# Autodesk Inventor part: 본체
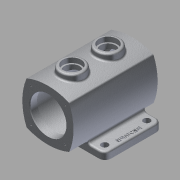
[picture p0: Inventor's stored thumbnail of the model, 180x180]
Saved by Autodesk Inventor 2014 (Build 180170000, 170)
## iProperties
Created: 2013-02
Part Number: 본체
Document SubType Name: Modeling
Designer: 한국산업디자인학원[gmhk.co.kr]
Density: 2.71 g/cm^3
Material: 알루미늄 6061
Mass: 1212.59 g
Surface Area: 1019.32 cm^2
Volume: 447.452 cm^3
Appearance: _시험_알루미늄 표면거칠기
Author: 한국산업디자인학원[gmhk.co.kr]
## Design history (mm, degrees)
sketch "스케치1"
  geometry: L1 (-65, 55)-(65, 55); L2 (65, 55)-(65, -40); L3 (65, -40)-(-65, -40); L4 (-65, -40)-(-65, 55); 2 further points
  constraints: 8 end point, 2 parallel, 1 horizontal, 1 midpoint, 1 perpendicular, 1 vertical alignment
  dimensions: "d0" = 130 distance of L2.end L3.end; "d1" = 95 distance of L1.end L2.end; "d47" = 40 distance from line of L3 point (0, 0)
extrude "돌출1" new body sketch "스케치1" distance "d2" = 12; taper "d3" = 0 deg
sketch "스케치2"
  geometry: L1 (-35.355, 85.355)-(35.355, 85.355); L2 (35.355, 85.355)-(35.355, 14.645); L3 (35.355, 14.645)-(-35.355, 14.645); L4 (-35.355, 14.645)-(-35.355, 85.355); L5 (35.355, 85.355)-(-35.355, 14.645); L6 (65, 0)-(-65, 0) reference; A1 r 91.05 centre (0, 1.45) between (35.355, 85.355) and (-35.355, 85.355); A2 r 91.05 centre (-48.55, 50) between (35.355, 14.645) and (35.355, 85.355); A3 r 91.05 centre (0, 98.55) between (-35.355, 14.645) and (35.355, 14.645); A4 r 91.05 centre (48.55, 50) between (-35.355, 85.355) and (-35.355, 14.645); 3 further points
  constraints: 10 end point, 8 point on circle, 4 centre point, 3 equal radius, 2 midpoint, 2 parallel, 2 perpendicular, 1 horizontal, 1 vertical alignment
  dimensions: "d4" = 50 distance from line of point (0, 50) L6; "d5" = 50 distance of L1.start point (0, 50); "d6" = 85 dimension on A2 A4
extrude "돌출2" join sketch "스케치2" stored distance "d7" = 140; taper "d8" = 0 deg
sketch "스케치3"
  geometry: L1 (28.27, 12)-(65, 12) reference; L2 (-65, 12)-(-28.27, 12) reference; A1 r 91.05 centre (0, 98.55) between (-35.355, 14.645) and (35.355, 14.645) reference; A2 r 91.05 centre (48.55, 50) between (-35.355, 85.355) and (-35.355, 14.645) reference; A3 r 91.05 centre (-48.55, 50) between (35.355, 14.645) and (35.355, 85.355) reference; A4 r 5 centre (-41.653, 17) between (-41.653, 12) and (-36.957, 18.718); A5 r 5 centre (41.653, 17) between (36.957, 18.718) and (41.653, 12); 1 further point
  constraints: 6 point on circle, 4 tangent, 2 centre point, 2 point on line, 1 equal radius
  dimensions: "d9" = 5 radius of A5
extrude "돌출3" join sketch "스케치3" stored distance "d10" = 120; taper "d11" = 0 deg
fillet "모깎기1" dims "d12" = 3
fillet "모깎기2" dims "d13" = 10
fillet "모깎기3" dims "d14" = 3
sketch "스케치4"
  geometry: L1 (-70, 84.185)-(-70, 85.839) reference; L2 (-70, 15.815)-(-70, 84.185) reference; L3 (-70, 14.161)-(-70, 15.815) reference; L4 (-70, 14.161)-(-70, 14.161) reference; L5 (-70, 15.815)-(-70, 14.161) reference; L6 (-70, 84.185)-(-70, 15.815) reference; L7 (-70, 85.839)-(-70, 84.185) reference; L8 (-70, 85.839)-(-70, 85.839) reference; L9 (70, 15.815)-(70, 14.161) reference; L10 (70, 84.185)-(70, 15.815) reference; L11 (70, 85.839)-(70, 84.185) reference; L12 (70, 85.839)-(70, 85.839) reference; L13 (70, 84.185)-(70, 85.839) reference; L14 (70, 15.815)-(70, 84.185) reference; L15 (70, 14.161)-(70, 15.815) reference; L16 (70, 14.161)-(70, 14.161) reference; L17 (-70, 50)-(70, 50); L18 (-70, 80)-(-58, 80); L19 (-58, 80)-(-58, 87.5); L20 (-58, 87.5)-(58, 87.5); L21 (58, 87.5)-(58, 80); L22 (58, 80)-(70, 80); 1 further point
  constraints: 12 end point, 2 collinear, 2 midpoint, 2 parallel, 2 perpendicular, 2 point on line
  dimensions: "d15" = 60 diameter of L18 L17; "d16" = 75 diameter of L20 L17; "d17" = 12 distance of L18.start L18.end; "d18" = 12 distance of L21.end L22.end
revolve "회전1" sketch "스케치4" stored, may be unused: angle "d19" = 90 deg
fillet "모깎기4" dims "d20" = 3
node "작업 평면2"
  node "작업 평면1"
sketch "스케치5"
  geometry: C1 r 20 at (0, 30); C2 r 20 at (0, -30); 1 further point
  constraints: 2 centre point, 2 vertical alignment
  dimensions: "d22" = 40 diameter of C1; "d23" = 40 diameter of C2; "d24" = 60 distance of C2.centre C1.centre; "d25" = 30 distance of point (0, 0) C1.centre (= 0.5 x d24)
extrude "돌출4" join sketch "스케치5" stored distance "d26" = 120; taper "d27" = 0 deg
fillet "모깎기5" dims "d28" = 3
hole "구멍1" diameter "d31" = 25; stored, may be unused: countersink angle "d35" = 90 deg, drill point angle "d37" = 118 deg; dims "d29" = 10, "d30" = 10, "d32" = 6, "d33" = 30, "d34" = 8, "d36" = 8
hole "구멍2" diameter "d40" = 25; stored, may be unused: countersink angle "d44" = 90 deg, drill point angle "d46" = 118 deg; dims "d38" = 10, "d39" = 10, "d41" = 6, "d42" = 30, "d43" = 8, "d45" = 8
sketch "스케치6"
  geometry: L1 (65, -30)-(65, 45) reference; 4 further points
  constraints: 1 midpoint, 1 vertical alignment
  dimensions: "d48" = 13 distance from line of point (52, 42.5) L1; "d49" = 70 distance of point (52, -27.5) point (52, 42.5); "d50" = 35 vertical distance of point (65, 7.5) point (52, 42.5) (= 0.5 x d49)
hole "구멍3" sketch "스케치6" at (52, -27.5), (52, 42.5) diameter "d51" = 11; stored, may be unused: countersink angle "d55" = 90 deg, drill point angle "d57" = 118 deg; dims "d52" = 6, "d53" = 30, "d54" = 8, "d56" = 8
sketch "스케치8"
  geometry: L1 (65, -30)-(65, 45) reference; 3 further points
  constraints: 1 horizontal alignment, 1 midpoint, 1 other
  dimensions: "d60" = 8 distance from line of point (57, 7.5) L1
feature "엠보싱2" sketch "스케치8" dims "d0" = 130, "d1" = 95, "d47" = 40, "d61" = 1, "d62" = 0
chamfer "모따기1" distance "d63" = 1; stored, may be unused: second distance "d64" = 2, angle "d65" = 45 deg
sketch "스케치9" dims "d9" = 5, "d75" = 40, "d76" = 360 deg
  geometry: L1 (0, 81)-(0, 50); L2 (0, 50)-(28.284, 78.284); 1 further point
  constraints: 4 end point, 1 vertical, 1 vertical alignment, 1 other
  dimensions: "d66" = 45 deg angle of L2 L1; "d67" = 40 distance of L2.end L1.end
hole "구멍4" sketch "스케치9" at (28.284, 78.284) diameter "d68" = 3.242; stored, may be unused: countersink angle "d72" = 90 deg, drill point angle "d74" = 118 deg; dims "d69" = 8, "d70" = 30, "d71" = 8, "d73" = 10
node "솔리드1"
mirror "대칭1"
pattern_circular "원형 패턴1" dims angle "d76" = 360 deg
mirror "대칭2"
node "투영된 루프1"
node "투영된 루프2"
